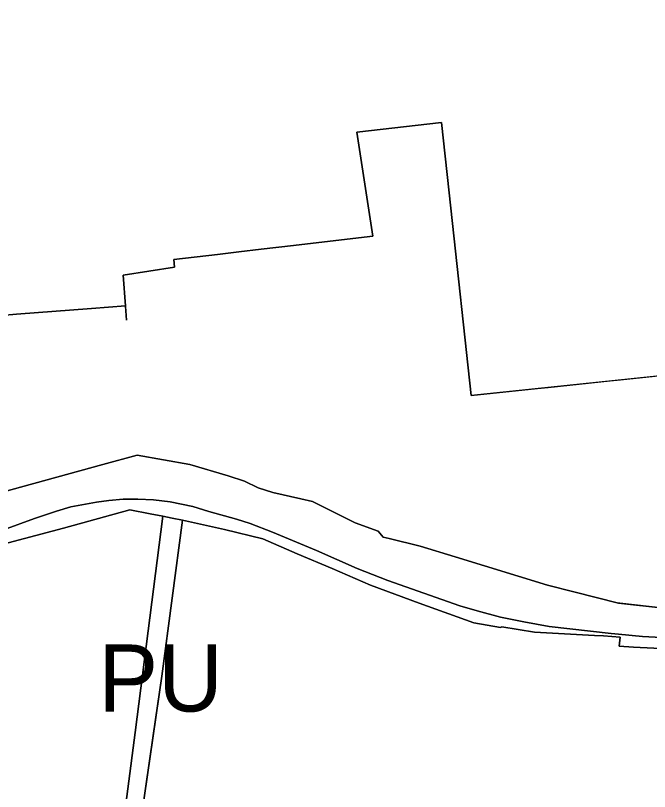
# Model space of a CAD drawing. Extents: x -555509 to -553005, y -1186756 to -1182560.
# Drawn here: x -554883.5 to -554751, y -1184543.3 to -1184381.2 of the extents above; entities that cross this region are included whole.
import ezdxf

# ---------------------------------------------------------------- set-up
doc = ezdxf.new("R2010")
doc.units = 0
for name, color, linetype in [('Level 15', 7, 'Continuous'), ('Level 36', 7, 'Continuous'), ('Level 52', 7, 'Continuous'), ('Level 59', 7, 'Continuous'), ('Level 6', 7, 'Continuous'), ('OBRYS_PLOCH', 7, 'Continuous'), ('stav_BV', 7, 'Continuous'), ('stav_DS', 7, 'Continuous'), ('stav_PU', 7, 'Continuous'), ('stav_ZZ', 7, 'Continuous')]:
    doc.layers.add(name, color=color, linetype=linetype)

msp = doc.modelspace()

# ---------------------------------------------------------------- linework, layer by layer
at = {"layer": 'Level 15'}
for points in [[(-554858.06, -1184473), (-554865.25, -1184474.97)], [(-554847.04, -1184474.94), (-554858.06, -1184473)], [(-554865.25, -1184474.97), (-554879.7, -1184478.93), (-554891.84, -1184482.26), (-554898.73, -1184485.38), (-554905.61, -1184488.47), (-554916.8, -1184493.18), (-554921.47, -1184495.24)], [(-554839.05, -1184477.29), (-554847.04, -1184474.94)], [(-554832.81, -1184479.85), (-554835.64, -1184478.43), (-554839.05, -1184477.29)], [(-554829.7, -1184480.83), (-554832.81, -1184479.85)], [(-554812.56, -1184487.1), (-554817.11, -1184484.82), (-554821.47, -1184482.66), (-554823.88, -1184482.12), (-554829.7, -1184480.83)], [(-555013.8, -1184540.42), (-555012.42, -1184540.17), (-555008.74, -1184539.35), (-555005.64, -1184538.67), (-555002.84, -1184537.61), (-554988.37, -1184534.54), (-554986.66, -1184533.56), (-554981.7, -1184532.14), (-554977.6, -1184530.5), (-554968.1, -1184526.69), (-554958.6, -1184522.89), (-554949.1, -1184519.08), (-554947.81, -1184518.56), (-554939.64, -1184515.13), (-554929.04, -1184510.68), (-554920.55, -1184506.92), (-554910.97, -1184502.68), (-554901.38, -1184498.43), (-554893.39, -1184494.72), (-554887.46, -1184491.97), (-554873.47, -1184488.25), (-554859.58, -1184484.45), (-554855.36, -1184485.24)], [(-554854.72, -1184531.53), (-554852.94, -1184519.18), (-554848.59, -1184486.57), (-554850.76, -1184486.13), (-554852.72, -1184485.74), (-554858.52, -1184530.92), (-554861.33, -1184552.85)], [(-554855.36, -1184485.24), (-554852.72, -1184485.74), (-554850.76, -1184486.13), (-554848.59, -1184486.57)], [(-554848.59, -1184486.57), (-554839.85, -1184488.53), (-554831.83, -1184490.5), (-554824.65, -1184493.64), (-554817.33, -1184496.67), (-554809.35, -1184500.16), (-554799.15, -1184503.89), (-554787.74, -1184508.06), (-554782.17, -1184509.03), (-554781.89, -1184508.87)], [(-554807.73, -1184488.86), (-554812.56, -1184487.1)], [(-554746.28, -1184504.15), (-554747.17, -1184504.55), (-554748.06, -1184504.95), (-554757.52, -1184503.92), (-554766.86, -1184501.55), (-554772.36, -1184500.16), (-554791.66, -1184494.22), (-554798.98, -1184492.03), (-554805.45, -1184490.44), (-554806.7, -1184490.13), (-554807.73, -1184488.86)], [(-554781.89, -1184508.87), (-554775.05, -1184509.95), (-554762.51, -1184510.68), (-554760.65, -1184510.75), (-554757.19, -1184510.99), (-554757.41, -1184512.9)], [(-554757.41, -1184512.9), (-554754.4, -1184513.13), (-554750.1, -1184513.32), (-554744.31, -1184513.39), (-554743.58, -1184513.52), (-554736.79, -1184514.11), (-554726.04, -1184515.23)], [(-554857.78, -1184552.7), (-554854.72, -1184531.53)]]:
    msp.add_lwpolyline(points, dxfattribs=at)
at = {"layer": 'Level 36'}
msp.add_lwpolyline([(-554724.18, -1184453.83), (-554788.3, -1184460.55), (-554792.53, -1184421.4), (-554794.47, -1184403.51), (-554812.15, -1184405.49), (-554808.84, -1184427.26), (-554813.02, -1184427.75), (-554825.4, -1184429.2), (-554832.16, -1184429.99), (-554836.85, -1184430.55), (-554841.29, -1184431.07), (-554850.41, -1184432.14), (-554850.29, -1184433.72), (-554861.02, -1184435.36), (-554860.52, -1184441.79), (-554867.61, -1184442.33), (-554883.32, -1184443.52), (-554888.8, -1184444.04)], dxfattribs=at)
at = {"layer": 'Level 52'}
msp.add_lwpolyline([(-554724.18, -1184453.83), (-554788.3, -1184460.55), (-554792.53, -1184421.4), (-554794.47, -1184403.51), (-554812.15, -1184405.49), (-554808.84, -1184427.26), (-554813.02, -1184427.75), (-554825.4, -1184429.2), (-554832.16, -1184429.99), (-554836.85, -1184430.55), (-554841.29, -1184431.07), (-554850.41, -1184432.14), (-554850.29, -1184433.72), (-554861.02, -1184435.36), (-554860.52, -1184441.79), (-554867.61, -1184442.33), (-554883.32, -1184443.52), (-554888.8, -1184444.04)], dxfattribs=at)
at = {"layer": 'Level 6'}
msp.add_lwpolyline([(-554724.18, -1184453.83), (-554788.3, -1184460.55), (-554792.53, -1184421.4), (-554794.47, -1184403.51), (-554812.15, -1184405.49), (-554808.84, -1184427.26), (-554813.02, -1184427.75), (-554825.4, -1184429.2), (-554832.16, -1184429.99), (-554836.85, -1184430.55), (-554841.29, -1184431.07), (-554850.41, -1184432.14), (-554850.29, -1184433.72), (-554861.02, -1184435.36), (-554860.52, -1184441.79), (-554867.61, -1184442.33), (-554883.32, -1184443.52), (-554888.8, -1184444.04)], dxfattribs=at)
at = {"layer": 'OBRYS_PLOCH'}
for p, q in [((-554808.84, -1184427.26), (-554812.15, -1184405.49)), ((-554792.53, -1184421.4), (-554788.3, -1184460.55)), ((-554825.4, -1184429.2), (-554813.02, -1184427.75)), ((-554813.02, -1184427.75), (-554808.84, -1184427.26)), ((-554832.16, -1184429.99), (-554825.4, -1184429.2)), ((-554841.29, -1184431.07), (-554836.85, -1184430.55)), ((-554836.85, -1184430.55), (-554832.16, -1184429.99)), ((-554861.02, -1184435.36), (-554850.29, -1184433.72)), ((-554861.02, -1184435.36), (-554860.28, -1184444.82)), ((-554860.52, -1184441.79), (-554861.02, -1184435.36)), ((-554883.32, -1184443.52), (-554867.61, -1184442.33)), ((-554860.52, -1184441.79), (-554867.61, -1184442.33)), ((-554867.61, -1184442.33), (-554860.52, -1184441.79)), ((-554860.28, -1184444.82), (-554860.52, -1184441.79)), ((-554888.8, -1184444.04), (-554883.32, -1184443.52)), ((-554757.82, -1184457.35), (-554755.79, -1184457.14)), ((-554755.79, -1184457.14), (-554743.17, -1184455.82)), ((-554772.19, -1184458.86), (-554759.24, -1184457.5)), ((-554759.24, -1184457.5), (-554757.82, -1184457.35)), ((-554788.3, -1184460.55), (-554774.47, -1184459.1)), ((-554774.47, -1184459.1), (-554772.19, -1184458.86)), ((-554865.25, -1184474.97), (-554858.06, -1184473)), ((-554858.06, -1184473), (-554865.25, -1184474.97)), ((-554847.04, -1184474.94), (-554858.06, -1184473)), ((-554865.25, -1184474.97), (-554879.7, -1184478.93)), ((-554839.05, -1184477.29), (-554847.04, -1184474.94)), ((-554879.7, -1184478.93), (-554891.84, -1184482.26)), ((-554829.7, -1184480.83), (-554832.81, -1184479.85)), ((-554823.88, -1184482.12), (-554829.7, -1184480.83)), ((-554871.91, -1184483.81), (-554866.6, -1184482.83)), ((-554866.6, -1184482.83), (-554871.91, -1184483.81)), ((-554866.6, -1184482.83), (-554863.99, -1184482.47)), ((-554863.99, -1184482.47), (-554866.6, -1184482.83)), ((-554863.99, -1184482.47), (-554860.97, -1184482.2)), ((-554860.97, -1184482.2), (-554863.99, -1184482.47)), ((-554860.97, -1184482.2), (-554857.95, -1184482.21)), ((-554857.95, -1184482.21), (-554860.97, -1184482.2)), ((-554857.95, -1184482.21), (-554854.67, -1184482.32)), ((-554854.67, -1184482.32), (-554857.95, -1184482.21)), ((-554854.67, -1184482.32), (-554851.15, -1184482.78)), ((-554851.15, -1184482.78), (-554854.67, -1184482.32)), ((-554851.15, -1184482.78), (-554846.46, -1184483.72)), ((-554846.46, -1184483.72), (-554851.15, -1184482.78)), ((-554821.47, -1184482.66), (-554823.88, -1184482.12)), ((-554817.11, -1184484.82), (-554821.47, -1184482.66)), ((-554879.53, -1184486.25), (-554874.96, -1184484.68)), ((-554874.96, -1184484.68), (-554879.53, -1184486.25)), ((-554874.96, -1184484.68), (-554871.91, -1184483.81)), ((-554871.91, -1184483.81), (-554874.96, -1184484.68)), ((-554859.58, -1184484.45), (-554873.47, -1184488.25)), ((-554855.36, -1184485.24), (-554859.58, -1184484.45)), ((-554846.46, -1184483.72), (-554843.09, -1184484.76)), ((-554843.09, -1184484.76), (-554846.46, -1184483.72)), ((-554843.09, -1184484.76), (-554837.32, -1184486.35)), ((-554837.32, -1184486.35), (-554843.09, -1184484.76)), ((-554885.99, -1184488.59), (-554879.53, -1184486.25)), ((-554879.53, -1184486.25), (-554885.99, -1184488.59)), ((-554858.52, -1184530.92), (-554852.72, -1184485.74)), ((-554855.36, -1184485.24), (-554852.72, -1184485.74)), ((-554852.72, -1184485.74), (-554855.36, -1184485.24)), ((-554837.32, -1184486.35), (-554834.47, -1184487.29)), ((-554834.47, -1184487.29), (-554837.32, -1184486.35)), ((-554812.56, -1184487.1), (-554817.11, -1184484.82)), ((-554834.47, -1184487.29), (-554829.79, -1184489.07)), ((-554829.79, -1184489.07), (-554834.47, -1184487.29)), ((-554807.73, -1184488.86), (-554812.56, -1184487.1)), ((-554873.47, -1184488.25), (-554887.46, -1184491.97)), ((-554829.79, -1184489.07), (-554820.59, -1184492.94)), ((-554820.59, -1184492.94), (-554829.79, -1184489.07)), ((-554806.7, -1184490.13), (-554807.73, -1184488.86)), ((-554805.45, -1184490.44), (-554806.7, -1184490.13)), ((-554798.98, -1184492.03), (-554805.45, -1184490.44)), ((-554791.66, -1184494.22), (-554798.98, -1184492.03)), ((-554820.59, -1184492.94), (-554812.1, -1184496.64)), ((-554812.1, -1184496.64), (-554820.59, -1184492.94)), ((-554772.36, -1184500.16), (-554791.66, -1184494.22)), ((-554812.1, -1184496.64), (-554805.73, -1184499.21)), ((-554805.73, -1184499.21), (-554812.1, -1184496.64)), ((-554805.73, -1184499.21), (-554790.64, -1184504.49)), ((-554790.64, -1184504.49), (-554805.73, -1184499.21)), ((-554766.86, -1184501.55), (-554772.36, -1184500.16)), ((-554757.52, -1184503.92), (-554766.86, -1184501.55)), ((-554757.24, -1184503.95), (-554757.52, -1184503.92)), ((-554790.64, -1184504.49), (-554787.07, -1184505.52)), ((-554787.07, -1184505.52), (-554790.64, -1184504.49)), ((-554787.07, -1184505.52), (-554782.18, -1184506.84)), ((-554782.18, -1184506.84), (-554787.07, -1184505.52)), ((-554782.18, -1184506.84), (-554777.27, -1184507.8)), ((-554777.27, -1184507.8), (-554782.18, -1184506.84)), ((-554777.27, -1184507.8), (-554771.99, -1184508.81)), ((-554771.99, -1184508.81), (-554777.27, -1184507.8)), ((-554771.99, -1184508.81), (-554759.07, -1184510.23)), ((-554759.07, -1184510.23), (-554771.99, -1184508.81)), ((-554759.07, -1184510.23), (-554757.49, -1184510.4)), ((-554757.49, -1184510.4), (-554759.07, -1184510.23)), ((-554757.49, -1184510.4), (-554752.52, -1184510.88)), ((-554752.52, -1184510.88), (-554757.49, -1184510.4)), ((-554752.52, -1184510.88), (-554744.35, -1184511.28)), ((-554744.35, -1184511.28), (-554752.52, -1184510.88)), ((-554861.33, -1184552.85), (-554858.52, -1184530.92)), ((-554857.78, -1184552.7), (-554854.72, -1184531.53))]:
    msp.add_line(p, q, dxfattribs=at)
for points in [[(-554639.28, -1184381.15), (-554638.44, -1184403.84), (-554637.94, -1184420.98), (-554635.54, -1184438.95), (-554639.94, -1184439.16), (-554642.71, -1184439.5), (-554644.5, -1184439.63), (-554644.06, -1184444.05), (-554651.87, -1184444.95), (-554661.09, -1184446.08), (-554670.78, -1184447.34), (-554706.42, -1184451.63), (-554724.18, -1184453.83), (-554788.3, -1184460.55)], [(-554788.3, -1184460.55), (-554792.53, -1184421.4), (-554794.47, -1184403.51), (-554812.15, -1184405.49), (-554808.84, -1184427.26), (-554813.02, -1184427.75)], [(-554812.15, -1184405.49), (-554794.47, -1184403.51), (-554792.53, -1184421.4)], [(-554813.02, -1184427.75), (-554825.4, -1184429.2), (-554832.16, -1184429.99), (-554836.85, -1184430.55), (-554841.29, -1184431.07), (-554850.41, -1184432.14), (-554850.29, -1184433.72), (-554861.02, -1184435.36)], [(-554867.61, -1184442.33), (-554883.32, -1184443.52), (-554888.8, -1184444.04), (-554889.77, -1184432.98), (-554925.29, -1184428.22), (-554924.8, -1184434.01), (-554924.65, -1184435.72), (-554924.15, -1184441.36), (-554922.9, -1184455.52), (-554929.41, -1184456.14), (-554939.69, -1184457.11), (-554941.7, -1184457.31)], [(-554850.29, -1184433.72), (-554850.41, -1184432.14), (-554841.29, -1184431.07)], [(-554858.06, -1184473), (-554847.04, -1184474.94), (-554839.05, -1184477.29), (-554835.64, -1184478.43), (-554832.81, -1184479.85), (-554829.7, -1184480.83), (-554823.88, -1184482.12), (-554821.47, -1184482.66), (-554817.11, -1184484.82), (-554812.56, -1184487.1), (-554807.73, -1184488.86)], [(-554921.47, -1184495.24), (-554916.8, -1184493.18), (-554905.61, -1184488.47), (-554898.73, -1184485.38), (-554891.84, -1184482.26), (-554879.7, -1184478.93), (-554865.25, -1184474.97)], [(-554832.81, -1184479.85), (-554835.64, -1184478.43), (-554839.05, -1184477.29)], [(-555008.74, -1184539.35), (-555005.64, -1184538.67), (-555002.84, -1184537.61), (-554988.37, -1184534.54), (-554986.66, -1184533.56), (-554981.7, -1184532.14), (-554977.6, -1184530.5), (-554968.1, -1184526.69), (-554958.6, -1184522.89), (-554949.1, -1184519.08), (-554947.81, -1184518.56), (-554939.64, -1184515.13), (-554929.04, -1184510.68), (-554920.55, -1184506.92), (-554910.97, -1184502.68), (-554901.38, -1184498.43), (-554893.39, -1184494.72), (-554887.46, -1184491.97), (-554873.47, -1184488.25), (-554859.58, -1184484.45), (-554855.36, -1184485.24)], [(-554852.72, -1184485.74), (-554858.52, -1184530.92), (-554861.33, -1184552.85)], [(-554781.89, -1184508.87), (-554782.17, -1184509.03), (-554787.74, -1184508.06), (-554799.15, -1184503.89), (-554809.35, -1184500.16), (-554817.33, -1184496.67), (-554824.65, -1184493.64), (-554831.83, -1184490.5), (-554839.85, -1184488.53), (-554848.59, -1184486.57), (-554852.94, -1184519.18), (-554857.78, -1184552.7)], [(-554854.72, -1184531.53), (-554852.94, -1184519.18), (-554848.59, -1184486.57)], [(-554848.59, -1184486.57), (-554839.85, -1184488.53), (-554831.83, -1184490.5), (-554824.65, -1184493.64), (-554817.33, -1184496.67), (-554809.35, -1184500.16), (-554799.15, -1184503.89), (-554787.74, -1184508.06), (-554782.17, -1184509.03), (-554781.89, -1184508.87)], [(-554807.73, -1184488.86), (-554806.7, -1184490.13), (-554805.45, -1184490.44), (-554798.98, -1184492.03), (-554791.66, -1184494.22), (-554772.36, -1184500.16)], [(-554772.36, -1184500.16), (-554766.86, -1184501.55), (-554757.52, -1184503.92), (-554748.06, -1184504.95), (-554747.17, -1184504.55), (-554746.28, -1184504.15)], [(-554747.17, -1184504.55), (-554748.06, -1184504.95), (-554757.24, -1184503.95)], [(-554757.41, -1184512.9), (-554757.19, -1184510.99), (-554760.65, -1184510.75), (-554762.51, -1184510.68), (-554775.05, -1184509.95), (-554781.89, -1184508.87)], [(-554781.89, -1184508.87), (-554775.05, -1184509.95), (-554762.51, -1184510.68), (-554760.65, -1184510.75), (-554757.19, -1184510.99), (-554757.41, -1184512.9)], [(-554726.04, -1184515.23), (-554736.79, -1184514.11), (-554743.58, -1184513.52), (-554744.31, -1184513.39), (-554750.1, -1184513.32), (-554754.4, -1184513.13), (-554757.41, -1184512.9)], [(-554757.41, -1184512.9), (-554754.4, -1184513.13), (-554750.1, -1184513.32), (-554744.31, -1184513.39), (-554743.58, -1184513.52), (-554736.79, -1184514.11), (-554726.04, -1184515.23)]]:
    msp.add_lwpolyline(points, dxfattribs=at)
at = {"layer": 'stav_BV'}
for p, q in [((-554861.02, -1184435.36), (-554860.28, -1184444.82)), ((-554860.52, -1184441.79), (-554867.61, -1184442.33)), ((-554860.28, -1184444.82), (-554860.52, -1184441.79)), ((-554865.25, -1184474.97), (-554858.06, -1184473))]:
    msp.add_line(p, q, dxfattribs=at)
for points in [[(-554639.28, -1184381.15), (-554638.44, -1184403.84), (-554637.94, -1184420.98), (-554635.54, -1184438.95), (-554639.94, -1184439.16), (-554642.71, -1184439.5), (-554644.5, -1184439.63), (-554644.06, -1184444.05), (-554651.87, -1184444.95), (-554661.09, -1184446.08), (-554670.78, -1184447.34), (-554706.42, -1184451.63), (-554724.18, -1184453.83), (-554788.3, -1184460.55)], [(-554788.3, -1184460.55), (-554792.53, -1184421.4), (-554794.47, -1184403.51), (-554812.15, -1184405.49), (-554808.84, -1184427.26), (-554813.02, -1184427.75)], [(-554813.02, -1184427.75), (-554825.4, -1184429.2), (-554832.16, -1184429.99), (-554836.85, -1184430.55), (-554841.29, -1184431.07), (-554850.41, -1184432.14), (-554850.29, -1184433.72), (-554861.02, -1184435.36)], [(-554867.61, -1184442.33), (-554883.32, -1184443.52), (-554888.8, -1184444.04), (-554889.77, -1184432.98), (-554925.29, -1184428.22), (-554924.8, -1184434.01), (-554924.65, -1184435.72), (-554924.15, -1184441.36), (-554922.9, -1184455.52), (-554929.41, -1184456.14), (-554939.69, -1184457.11), (-554941.7, -1184457.31)], [(-554858.06, -1184473), (-554847.04, -1184474.94), (-554839.05, -1184477.29), (-554835.64, -1184478.43), (-554832.81, -1184479.85), (-554829.7, -1184480.83), (-554823.88, -1184482.12), (-554821.47, -1184482.66), (-554817.11, -1184484.82), (-554812.56, -1184487.1), (-554807.73, -1184488.86)], [(-554921.47, -1184495.24), (-554916.8, -1184493.18), (-554905.61, -1184488.47), (-554898.73, -1184485.38), (-554891.84, -1184482.26), (-554879.7, -1184478.93), (-554865.25, -1184474.97)], [(-554863.57, -1184552.94), (-554861.33, -1184552.85), (-554858.52, -1184530.92), (-554852.72, -1184485.74), (-554855.36, -1184485.24), (-554859.58, -1184484.45), (-554873.47, -1184488.25), (-554887.46, -1184491.97)], [(-554781.89, -1184508.87), (-554782.17, -1184509.03), (-554787.74, -1184508.06), (-554799.15, -1184503.89), (-554809.35, -1184500.16), (-554817.33, -1184496.67), (-554824.65, -1184493.64), (-554831.83, -1184490.5), (-554839.85, -1184488.53), (-554848.59, -1184486.57), (-554852.94, -1184519.18), (-554857.78, -1184552.7)], [(-554807.73, -1184488.86), (-554806.7, -1184490.13), (-554805.45, -1184490.44), (-554798.98, -1184492.03), (-554791.66, -1184494.22), (-554772.36, -1184500.16)], [(-554772.36, -1184500.16), (-554766.86, -1184501.55), (-554757.52, -1184503.92), (-554748.06, -1184504.95), (-554747.17, -1184504.55), (-554746.28, -1184504.15)], [(-554757.41, -1184512.9), (-554757.19, -1184510.99), (-554760.65, -1184510.75), (-554762.51, -1184510.68), (-554775.05, -1184509.95), (-554781.89, -1184508.87)], [(-554726.04, -1184515.23), (-554736.79, -1184514.11), (-554743.58, -1184513.52), (-554744.31, -1184513.39), (-554750.1, -1184513.32), (-554754.4, -1184513.13), (-554757.41, -1184512.9)]]:
    msp.add_lwpolyline(points, dxfattribs=at)
at = {"layer": 'stav_DS'}
for p, q in [((-554858.06, -1184473), (-554865.25, -1184474.97)), ((-554865.25, -1184474.97), (-554879.7, -1184478.93)), ((-554879.7, -1184478.93), (-554891.84, -1184482.26)), ((-554829.7, -1184480.83), (-554832.81, -1184479.85)), ((-554871.91, -1184483.81), (-554866.6, -1184482.83)), ((-554866.6, -1184482.83), (-554863.99, -1184482.47)), ((-554863.99, -1184482.47), (-554860.97, -1184482.2)), ((-554860.97, -1184482.2), (-554857.95, -1184482.21)), ((-554857.95, -1184482.21), (-554854.67, -1184482.32)), ((-554854.67, -1184482.32), (-554851.15, -1184482.78)), ((-554851.15, -1184482.78), (-554846.46, -1184483.72)), ((-554879.53, -1184486.25), (-554874.96, -1184484.68)), ((-554874.96, -1184484.68), (-554871.91, -1184483.81)), ((-554846.46, -1184483.72), (-554843.09, -1184484.76)), ((-554843.09, -1184484.76), (-554837.32, -1184486.35)), ((-554885.99, -1184488.59), (-554879.53, -1184486.25)), ((-554837.32, -1184486.35), (-554834.47, -1184487.29)), ((-554812.56, -1184487.1), (-554817.11, -1184484.82)), ((-554834.47, -1184487.29), (-554829.79, -1184489.07)), ((-554807.73, -1184488.86), (-554812.56, -1184487.1)), ((-554829.79, -1184489.07), (-554820.59, -1184492.94)), ((-554806.7, -1184490.13), (-554807.73, -1184488.86)), ((-554805.45, -1184490.44), (-554806.7, -1184490.13)), ((-554798.98, -1184492.03), (-554805.45, -1184490.44)), ((-554791.66, -1184494.22), (-554798.98, -1184492.03)), ((-554820.59, -1184492.94), (-554812.1, -1184496.64)), ((-554772.36, -1184500.16), (-554791.66, -1184494.22)), ((-554812.1, -1184496.64), (-554805.73, -1184499.21)), ((-554805.73, -1184499.21), (-554790.64, -1184504.49)), ((-554766.86, -1184501.55), (-554772.36, -1184500.16)), ((-554757.52, -1184503.92), (-554766.86, -1184501.55)), ((-554757.24, -1184503.95), (-554757.52, -1184503.92)), ((-554790.64, -1184504.49), (-554787.07, -1184505.52)), ((-554787.07, -1184505.52), (-554782.18, -1184506.84)), ((-554782.18, -1184506.84), (-554777.27, -1184507.8)), ((-554777.27, -1184507.8), (-554771.99, -1184508.81)), ((-554771.99, -1184508.81), (-554759.07, -1184510.23)), ((-554759.07, -1184510.23), (-554757.49, -1184510.4)), ((-554757.49, -1184510.4), (-554752.52, -1184510.88)), ((-554752.52, -1184510.88), (-554744.35, -1184511.28))]:
    msp.add_line(p, q, dxfattribs=at)
for points in [[(-554832.81, -1184479.85), (-554835.64, -1184478.43), (-554839.05, -1184477.29), (-554847.04, -1184474.94), (-554858.06, -1184473)], [(-554817.11, -1184484.82), (-554821.47, -1184482.66), (-554823.88, -1184482.12), (-554829.7, -1184480.83)], [(-554747.17, -1184504.55), (-554748.06, -1184504.95), (-554757.24, -1184503.95)]]:
    msp.add_lwpolyline(points, dxfattribs=at)
at = {"layer": 'stav_PU'}
for p, q in [((-554858.06, -1184473), (-554865.25, -1184474.97)), ((-554847.04, -1184474.94), (-554858.06, -1184473)), ((-554839.05, -1184477.29), (-554847.04, -1184474.94)), ((-554829.7, -1184480.83), (-554832.81, -1184479.85)), ((-554855.36, -1184485.24), (-554852.72, -1184485.74)), ((-554807.73, -1184488.86), (-554812.56, -1184487.1)), ((-554857.78, -1184552.7), (-554854.72, -1184531.53))]:
    msp.add_line(p, q, dxfattribs=at)
for points in [[(-554865.25, -1184474.97), (-554879.7, -1184478.93), (-554891.84, -1184482.26), (-554898.73, -1184485.38), (-554905.61, -1184488.47), (-554916.8, -1184493.18), (-554921.47, -1184495.24)], [(-554832.81, -1184479.85), (-554835.64, -1184478.43), (-554839.05, -1184477.29)], [(-554812.56, -1184487.1), (-554817.11, -1184484.82), (-554821.47, -1184482.66), (-554823.88, -1184482.12), (-554829.7, -1184480.83)], [(-555008.74, -1184539.35), (-555005.64, -1184538.67), (-555002.84, -1184537.61), (-554988.37, -1184534.54), (-554986.66, -1184533.56), (-554981.7, -1184532.14), (-554977.6, -1184530.5), (-554968.1, -1184526.69), (-554958.6, -1184522.89), (-554949.1, -1184519.08), (-554947.81, -1184518.56), (-554939.64, -1184515.13), (-554929.04, -1184510.68), (-554920.55, -1184506.92), (-554910.97, -1184502.68), (-554901.38, -1184498.43), (-554893.39, -1184494.72), (-554887.46, -1184491.97), (-554873.47, -1184488.25), (-554859.58, -1184484.45), (-554855.36, -1184485.24)], [(-554852.72, -1184485.74), (-554858.52, -1184530.92), (-554861.33, -1184552.85)], [(-554854.72, -1184531.53), (-554852.94, -1184519.18), (-554848.59, -1184486.57)], [(-554848.59, -1184486.57), (-554839.85, -1184488.53), (-554831.83, -1184490.5), (-554824.65, -1184493.64), (-554817.33, -1184496.67), (-554809.35, -1184500.16), (-554799.15, -1184503.89), (-554787.74, -1184508.06), (-554782.17, -1184509.03), (-554781.89, -1184508.87)], [(-554746.28, -1184504.15), (-554747.17, -1184504.55), (-554748.06, -1184504.95), (-554757.52, -1184503.92), (-554766.86, -1184501.55), (-554772.36, -1184500.16), (-554791.66, -1184494.22), (-554798.98, -1184492.03), (-554805.45, -1184490.44), (-554806.7, -1184490.13), (-554807.73, -1184488.86)], [(-554781.89, -1184508.87), (-554775.05, -1184509.95), (-554762.51, -1184510.68), (-554760.65, -1184510.75), (-554757.19, -1184510.99), (-554757.41, -1184512.9)], [(-554757.41, -1184512.9), (-554754.4, -1184513.13), (-554750.1, -1184513.32), (-554744.31, -1184513.39), (-554743.58, -1184513.52), (-554736.79, -1184514.11), (-554726.04, -1184515.23)]]:
    msp.add_lwpolyline(points, dxfattribs=at)
at = {"layer": 'stav_ZZ'}
for p, q in [((-554794.47, -1184403.51), (-554792.53, -1184421.4)), ((-554792.53, -1184421.4), (-554788.3, -1184460.55)), ((-554825.4, -1184429.2), (-554813.02, -1184427.75)), ((-554832.16, -1184429.99), (-554825.4, -1184429.2)), ((-554836.85, -1184430.55), (-554832.16, -1184429.99)), ((-554850.29, -1184433.72), (-554850.41, -1184432.14)), ((-554861.02, -1184435.36), (-554850.29, -1184433.72)), ((-554860.52, -1184441.79), (-554861.02, -1184435.36)), ((-554883.32, -1184443.52), (-554867.61, -1184442.33)), ((-554867.61, -1184442.33), (-554860.52, -1184441.79)), ((-554888.8, -1184444.04), (-554883.32, -1184443.52)), ((-554757.82, -1184457.35), (-554755.79, -1184457.14)), ((-554755.79, -1184457.14), (-554743.17, -1184455.82)), ((-554772.19, -1184458.86), (-554759.24, -1184457.5)), ((-554759.24, -1184457.5), (-554757.82, -1184457.35)), ((-554788.3, -1184460.55), (-554774.47, -1184459.1)), ((-554774.47, -1184459.1), (-554772.19, -1184458.86))]:
    msp.add_line(p, q, dxfattribs=at)
for points in [[(-554813.02, -1184427.75), (-554808.84, -1184427.26), (-554812.15, -1184405.49), (-554794.47, -1184403.51)], [(-554850.41, -1184432.14), (-554841.29, -1184431.07), (-554836.85, -1184430.55)]]:
    msp.add_lwpolyline(points, dxfattribs=at)

# ---------------------------------------------------------------- texts
at = {"layer": 'Level 59'}
msp.add_text('PU', height=14, dxfattribs=at).set_placement((-554866.18, -1184526.55))

doc.saveas('drawing.dxf')
